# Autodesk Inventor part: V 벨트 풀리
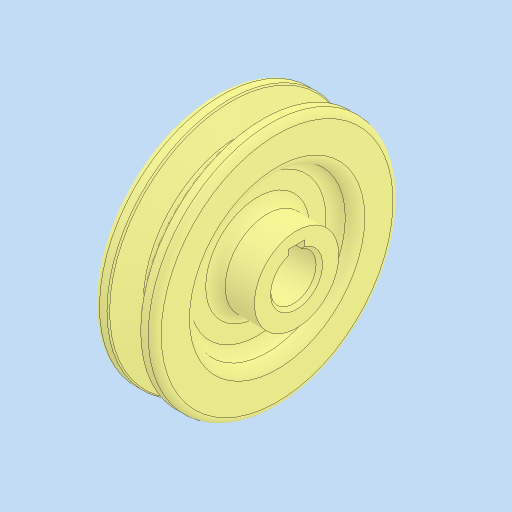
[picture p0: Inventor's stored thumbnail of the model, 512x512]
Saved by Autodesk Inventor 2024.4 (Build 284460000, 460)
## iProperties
Created: 2026-07
Part Number: V 벨트 풀리
Material: 강철, 주조
Document SubType Name: Modeling
Designer: home
Density: 7.85 g/cm^3
Appearance: 기본값
Author: jhkim
Sending System: Autodesk Inventor 2027
Preprocessor: ST-DEVELOPER v20.1
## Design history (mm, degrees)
feature "솔리드1"
node "솔리드2"
